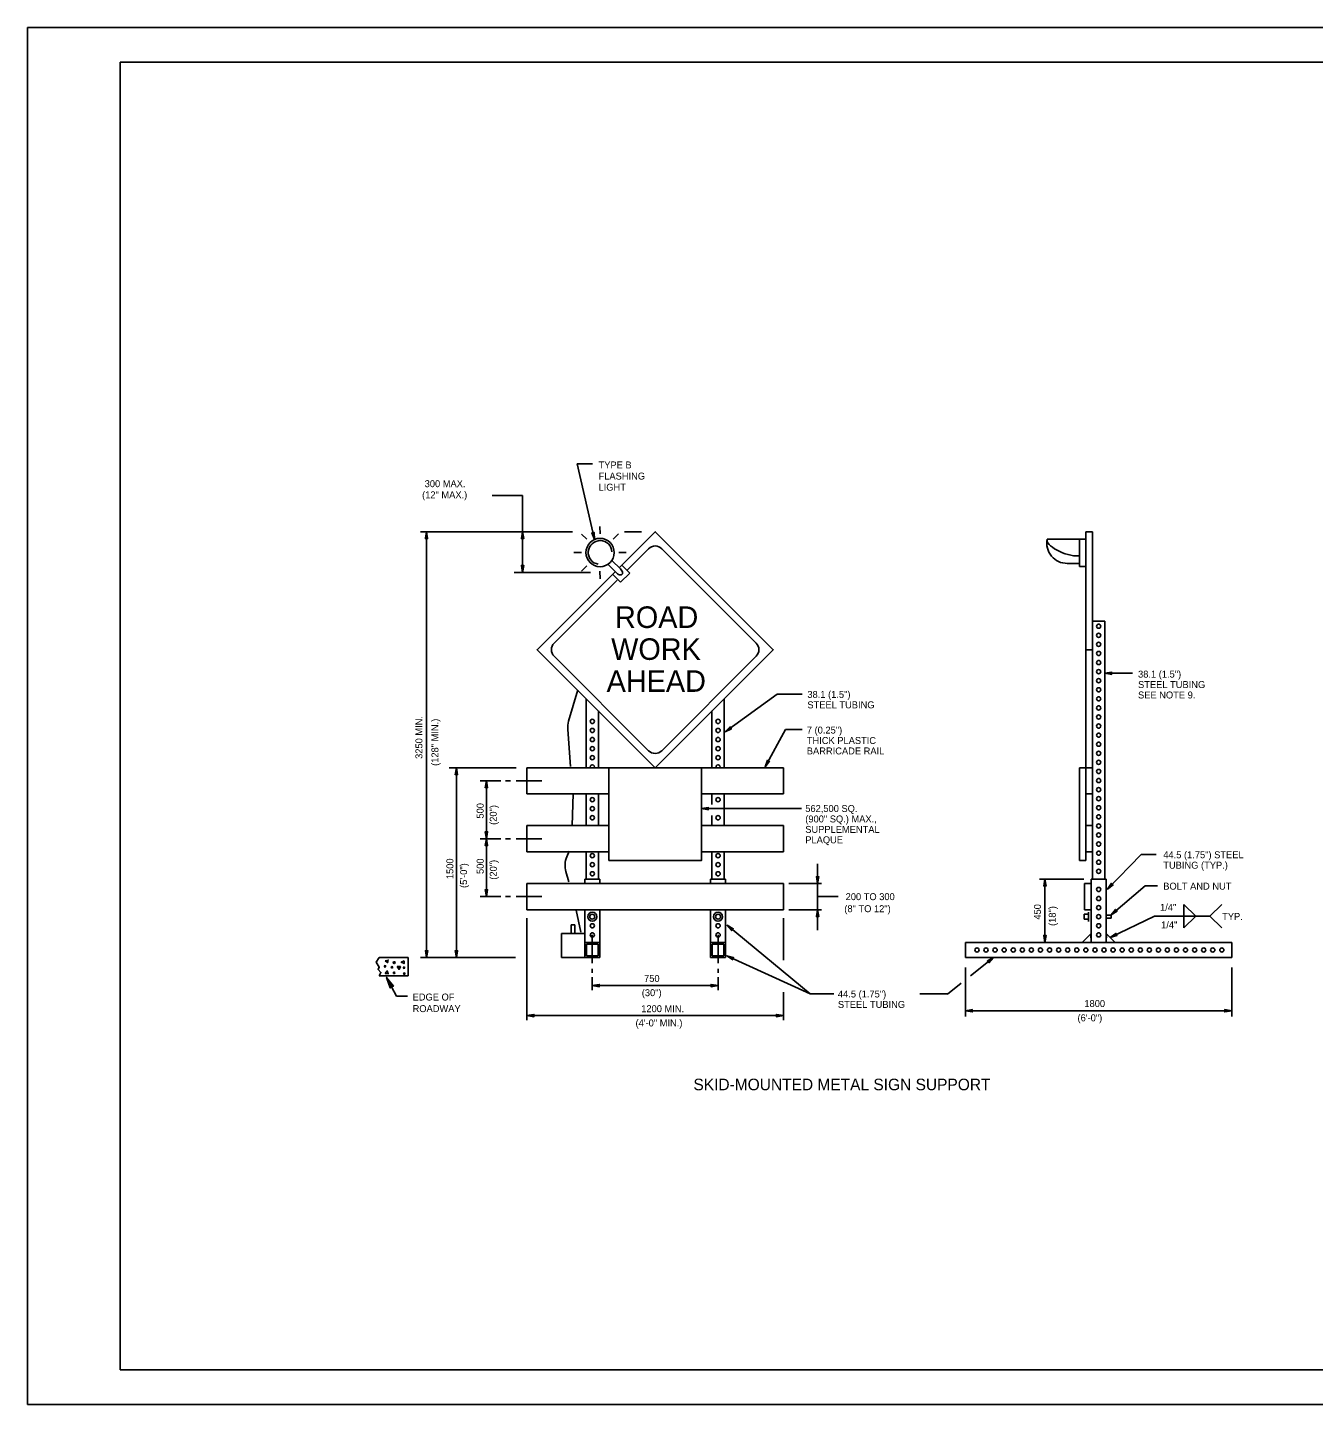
# Model space of a CAD drawing. Extents: x 641885 to 642995, y 293121 to 294294.
# Drawn here: x 641885 to 642440, y 293700 to 294294 of the extents above; entities that cross this region are included whole.
import ezdxf

# ---------------------------------------------------------------- set-up
doc = ezdxf.new("R2010")
doc.units = 0
for name, color, linetype in [('1', 7, 'Continuous'), ('Default', 7, 'Continuous'), ('Level 1', 7, 'Continuous'), ('Level 2', 7, 'Continuous'), ('Level 3', 7, 'Continuous'), ('PLT-BNDY', 7, 'Continuous')]:
    doc.layers.add(name, color=color, linetype=linetype)

# ---------------------------------------------------------------- blocks, each defined once
blk = doc.blocks.new('RARROW')
at = {"layer": 'Level 3'}
blk.add_lwpolyline([(-2.2695, 0.285), (-2.184875, 0.12075), (0, 0), (-2.2695, 0.285), (-2.38575, 0.384625), (0, 0), (-2.183125, -0.108), (-2.262875, -0.2705), (0, 0), (-2.38575, -0.379125), (-2.262875, -0.2705)], dxfattribs=at)

msp = doc.modelspace()

# ---------------------------------------------------------------- linework, layer by layer
at = {"layer": '1'}
for p, q in [((642384.2, 293910.28), (642384.2, 293915.37)), ((642389.3, 293910.28), (642384.2, 293915.37)), ((642395.44, 293910.28), (642400.54, 293915.37)), ((642371.58, 293910.28), (642395.44, 293910.28)), ((642384.2, 293910.28), (642384.2, 293905.18)), ((642389.3, 293910.28), (642384.2, 293905.18)), ((642395.44, 293910.28), (642400.54, 293905.18)), ((642040.24, 293883.86), (642044.56, 293875.8))]:
    msp.add_line(p, q, dxfattribs=at)
for points in [[(642037.06, 293892.46), (642035.66, 293890.45), (642037.02, 293888.25), (642036.56, 293887.27), (642037.78, 293885.98), (642037.06, 293884.47)], [(642041.88, 293879.59), (642042.09, 293879.89), (642040.24, 293883.86), (642041.88, 293879.59), (642041.81, 293879.29), (642040.24, 293883.86), (642042.49, 293880.11), (642042.85, 293880.13), (642040.24, 293883.86), (642043.16, 293880.01), (642042.85, 293880.13)]]:
    msp.add_lwpolyline(points, dxfattribs=at)
for points in [[(642039.67, 293890.98), (642040.96, 293891.36), (642040.65, 293890.22)], [(642044.74, 293888.56), (642046.18, 293888.56), (642045.58, 293887.27)], [(642047.77, 293891.06), (642047.77, 293889.84), (642046.56, 293890.37)], [(642039.59, 293885.6), (642040.96, 293885.45), (642040.5, 293886.66)]]:
    msp.add_lwpolyline(points, close=True, dxfattribs=at)
for centre, radius in [((642039.59, 293888.63), 0.321), ((642042.55, 293888.25), 0.321), ((642043.53, 293890.22), 0.408), ((642047.77, 293888.03), 0.321), ((642043.46, 293885.83), 0.321), ((642047.85, 293885.53), 0.321)]:
    msp.add_circle(centre, radius, dxfattribs=at)
at = {"layer": 'Default'}
for p, q in [((642049.48, 293892.46), (642037.06, 293892.46)), ((642049.48, 293892.46), (642049.48, 293884.47)), ((642049.48, 293884.47), (642037.06, 293884.47)), ((642044.56, 293875.8), (642049.17, 293875.8))]:
    msp.add_line(p, q, dxfattribs=at)
at = {"layer": 'Level 1'}
for p, q in [((641925.31, 294278.63), (642711.31, 294278.63)), ((641925.31, 294278.63), (641925.31, 293714.63)), ((642711.31, 293714.63), (641925.31, 293714.63)), ((641925.31, 293714.63), (642511.31, 293714.63))]:
    msp.add_line(p, q, dxfattribs=at)
at = {"layer": 'Level 2'}
for p, q in [((642122.46, 294105.39), (642129.1, 294105.39)), ((642122.46, 294105.39), (642129.94, 294072.78)), ((642085.79, 294091.69), (642098.9, 294091.69)), ((642098.9, 294091.69), (642098.9, 294058.57)), ((642132.3, 294075.22), (642132.28, 294078.43)), ((642054.87, 294076.13), (642120.37, 294076.13)), ((642057.44, 293892.46), (642057.44, 294076.13)), ((642126.6, 294072.84), (642124.32, 294075.09)), ((642138.01, 294072.88), (642140.27, 294075.15)), ((642142.84, 294076.13), (642150.19, 294076.13)), ((642325.24, 294072.95), (642341.94, 294072.95)), ((642339.12, 294072.95), (642339.12, 294061.13)), ((642341.94, 294076.13), (642341.94, 293974.31)), ((642341.94, 294076.13), (642344.76, 294076.13)), ((642344.76, 294076.13), (642344.76, 293974.31)), ((642124.25, 294067.12), (642121.05, 294067.11)), ((642140.4, 294067.18), (642143.6, 294067.19)), ((642153.27, 294068.8), (642144.17, 294059.69)), ((642199.67, 294028.05), (642158.92, 294068.8)), ((642126.56, 294061.44), (642124.31, 294059.17)), ((642139.37, 294058.38), (642135.7, 294062.06)), ((642141.1, 294060.1), (642137.42, 294063.78)), ((642145.17, 294058.29), (642141.71, 294061.75)), ((642333.91, 294062.46), (642339.12, 294062.46)), ((642339.12, 294061.13), (642341.94, 294061.13)), ((642095.3, 294058.57), (642128.15, 294058.57)), ((642139.64, 294055.17), (642112.52, 294028.05)), ((642132.29, 294059.04), (642132.3, 294055.84)), ((642141.18, 294054.31), (642137.73, 294057.77)), ((642141.18, 294054.31), (642145.17, 294058.29)), ((642344.76, 294037.6), (642350.06, 294037.6)), ((642350.06, 294037.6), (642350.06, 293926.28)), ((642341.94, 294025.22), (642344.76, 294025.22)), ((642112.52, 294022.39), (642153.27, 293981.65)), ((642158.92, 293981.65), (642199.67, 294022.39)), ((642350.06, 294015.06), (642362.08, 294015.06)), ((642122.69, 294007.93), (642118.76, 293994.37)), ((642126.31, 294004.1), (642126.31, 293974.31)), ((642185.88, 294004.1), (642185.88, 293974.31)), ((642208.67, 294005.98), (642186.27, 293989.8)), ((642208.67, 294005.98), (642219.48, 294005.98)), ((642131.61, 293998.79), (642131.61, 293974.31)), ((642180.58, 293998.79), (642180.58, 293974.31)), ((642118.39, 293990.87), (642119.53, 293974.79)), ((642212.27, 293990.85), (642203.55, 293974.67)), ((642212.27, 293990.85), (642219.44, 293990.85)), ((642067.19, 293974.31), (642096.15, 293974.31)), ((642070.37, 293892.46), (642070.37, 293974.31)), ((642100.79, 293974.31), (642136.1, 293974.31)), ((642100.79, 293974.31), (642100.79, 293963)), ((642211.4, 293974.31), (642176.1, 293974.31)), ((642211.4, 293974.31), (642211.4, 293963)), ((642339.12, 293974.31), (642344.76, 293974.31)), ((642339.12, 293974.31), (642339.12, 293934.31)), ((642341.94, 293974.31), (642341.94, 293934.31)), ((642344.76, 293974.31), (642344.76, 293926.28)), ((642089.48, 293968.66), (642080.61, 293968.66)), ((642083.3, 293943.69), (642083.3, 293968.66)), ((642093.67, 293968.66), (642091.45, 293968.66)), ((642107.21, 293968.66), (642096.13, 293968.66)), ((642100.79, 293963), (642136.1, 293963)), ((642120.7, 293963), (642120.25, 293949.34)), ((642126.31, 293963), (642126.31, 293949.34)), ((642131.61, 293963), (642131.61, 293949.34)), ((642211.4, 293963), (642176.1, 293963)), ((642180.58, 293963), (642180.58, 293958.46)), ((642185.88, 293963), (642185.88, 293949.34)), ((642341.94, 293963), (642344.76, 293963)), ((642176.1, 293956.68), (642219.2, 293956.68)), ((642180.58, 293953.71), (642180.58, 293949.34)), ((642100.79, 293949.34), (642136.1, 293949.34)), ((642100.79, 293949.34), (642100.79, 293938.03)), ((642211.4, 293949.34), (642176.1, 293949.34)), ((642211.4, 293949.34), (642211.4, 293938.03)), ((642341.94, 293949.34), (642344.76, 293949.34)), ((642089.48, 293943.69), (642080.61, 293943.69)), ((642083.3, 293918.71), (642083.3, 293943.69)), ((642093.67, 293943.69), (642091.45, 293943.69)), ((642107.21, 293943.69), (642096.13, 293943.69)), ((642100.79, 293938.03), (642136.1, 293938.03)), ((642118.95, 293938.35), (642117.95, 293935.92)), ((642126.31, 293938.03), (642126.31, 293926.28)), ((642131.61, 293938.03), (642131.61, 293926.28)), ((642211.4, 293938.03), (642176.1, 293938.03)), ((642180.58, 293938.03), (642180.58, 293926.28)), ((642185.88, 293938.03), (642185.88, 293926.28)), ((642341.94, 293938.03), (642344.76, 293938.03)), ((642351.23, 293921.97), (642365.7, 293936.86)), ((642365.7, 293936.86), (642372.29, 293936.86)), ((642117.56, 293929.5), (642118.78, 293925.03)), ((642226.18, 293924.37), (642226.18, 293932.79)), ((642339.12, 293934.31), (642341.94, 293934.31)), ((642100.79, 293924.37), (642211.4, 293924.37)), ((642100.79, 293924.37), (642100.79, 293913.06)), ((642132.21, 293926.28), (642125.71, 293926.28)), ((642125.71, 293924.37), (642125.71, 293926.28)), ((642132.21, 293924.37), (642132.21, 293926.28)), ((642186.48, 293926.28), (642179.98, 293926.28)), ((642179.98, 293924.37), (642179.98, 293926.28)), ((642186.48, 293924.37), (642186.48, 293926.28)), ((642211.4, 293924.37), (642211.4, 293913.06)), ((642213.69, 293924.37), (642227.87, 293924.37)), ((642226.18, 293913.06), (642226.18, 293924.37)), ((642321.91, 293926.28), (642341.05, 293926.28)), ((642324.23, 293898.96), (642324.23, 293926.28)), ((642344.16, 293924.37), (642341.34, 293924.37)), ((642341.34, 293924.37), (642341.34, 293913.06)), ((642344.16, 293926.28), (642344.16, 293898.96)), ((642344.16, 293926.28), (642350.66, 293926.28)), ((642350.66, 293926.28), (642350.66, 293898.96)), ((642352.77, 293910.89), (642367.46, 293923.42)), ((642367.46, 293923.42), (642372.86, 293923.42)), ((642089.48, 293918.71), (642080.61, 293918.71)), ((642093.67, 293918.71), (642091.45, 293918.71)), ((642107.21, 293918.71), (642096.13, 293918.71)), ((642226.18, 293918.71), (642235.1, 293918.71)), ((642100.79, 293913.06), (642211.4, 293913.06)), ((642122.07, 293912.89), (642124.01, 293903.39)), ((642125.71, 293892.46), (642125.71, 293913.06)), ((642132.21, 293892.46), (642132.21, 293913.06)), ((642179.98, 293892.46), (642179.98, 293913.06)), ((642186.48, 293892.46), (642186.48, 293913.06)), ((642213.69, 293913.06), (642227.87, 293913.06)), ((642226.18, 293904.26), (642226.18, 293913.06)), ((642344.16, 293913.06), (642341.34, 293913.06)), ((642343.07, 293912.02), (642343.07, 293907.92)), ((642100.79, 293865.41), (642100.79, 293909.38)), ((642119.86, 293902.8), (642119.86, 293906.5)), ((642119.86, 293906.5), (642121.46, 293906.5)), ((642121.46, 293902.8), (642121.46, 293906.5)), ((642223, 293876.74), (642187.13, 293906.38)), ((642211.4, 293891.25), (642211.4, 293909.38)), ((642343.07, 293911.11), (642341.23, 293911.11)), ((642341.23, 293911.11), (642341.23, 293908.97)), ((642343.07, 293908.97), (642341.23, 293908.97)), ((642352.82, 293910.66), (642350.66, 293910.66)), ((642352.82, 293909.42), (642350.66, 293909.42)), ((642352.41, 293901.05), (642371.58, 293910.28)), ((642352.82, 293910.66), (642352.82, 293909.42)), ((642115.61, 293902.8), (642125.71, 293902.8)), ((642115.61, 293902.8), (642115.61, 293892.46)), ((642125.71, 293902.8), (642125.71, 293892.46)), ((642128.96, 293890.04), (642128.96, 293902.21)), ((642183.23, 293890.04), (642183.23, 293902.21)), ((642132.21, 293898.96), (642125.71, 293898.96)), ((642126.46, 293893.21), (642126.46, 293898.21)), ((642131.46, 293898.21), (642126.46, 293898.21)), ((642131.46, 293893.21), (642131.46, 293898.21)), ((642186.48, 293898.96), (642179.98, 293898.96)), ((642180.73, 293893.21), (642180.73, 293898.21)), ((642185.73, 293898.21), (642180.73, 293898.21)), ((642185.73, 293893.21), (642185.73, 293898.21)), ((642289.96, 293898.96), (642404.86, 293898.96)), ((642289.96, 293898.96), (642289.96, 293892.46)), ((642404.86, 293898.96), (642404.86, 293892.46)), ((642054.87, 293892.46), (642095.88, 293892.46)), ((642115.61, 293892.46), (642125.71, 293892.46)), ((642132.21, 293892.46), (642125.71, 293892.46)), ((642131.46, 293893.21), (642126.46, 293893.21)), ((642128.96, 293885.8), (642128.96, 293887.52)), ((642186.48, 293892.46), (642179.98, 293892.46)), ((642185.73, 293893.21), (642180.73, 293893.21)), ((642183.23, 293885.8), (642183.23, 293887.52)), ((642223, 293876.74), (642187.02, 293893.19)), ((642289.96, 293892.46), (642404.86, 293892.46)), ((642289.96, 293867.01), (642289.96, 293888.2)), ((642292.13, 293884.57), (642302.1, 293892.46)), ((642404.86, 293867.01), (642404.86, 293888.2)), ((642128.96, 293878.34), (642128.96, 293883.89)), ((642183.23, 293878.34), (642183.23, 293883.89)), ((642128.96, 293880.31), (642183.23, 293880.31)), ((642211.4, 293865.41), (642211.4, 293877.44)), ((642223, 293876.74), (642233.15, 293876.74)), ((642270.25, 293876.74), (642282.25, 293876.74)), ((642282.18, 293876.69), (642288.11, 293881.38)), ((642100.79, 293867.38), (642211.4, 293867.38)), ((642289.96, 293869.48), (642404.86, 293869.48))]:
    msp.add_line(p, q, dxfattribs=at)
msp.add_lwpolyline([(642138.62, 294058.66), (642105.18, 294025.22), (642156.1, 293974.31), (642207.01, 294025.22), (642156.1, 294076.13), (642140.65, 294060.69)], dxfattribs=at)
for points in [[(642136.1, 293934.31), (642176.1, 293934.31), (642176.1, 293974.31), (642136.1, 293974.31)], [(642344.16, 293898.96), (642340.33, 293898.91), (642344.02, 293902.61)], [(642350.66, 293898.96), (642354.49, 293898.91), (642350.79, 293902.61)]]:
    msp.add_lwpolyline(points, close=True, dxfattribs=at)
for centre, radius in [((642132.33, 294067.15), 6.11), ((642347.41, 294035.36), 0.903), ((642347.41, 294031.44), 0.903), ((642347.41, 294027.52), 0.903), ((642347.41, 294023.61), 0.903), ((642347.41, 294019.69), 0.903), ((642347.41, 294015.77), 0.903), ((642347.41, 294011.86), 0.903), ((642347.41, 294007.94), 0.903), ((642347.41, 294004.03), 0.903), ((642347.41, 294000.11), 0.903), ((642128.96, 293994.29), 0.903), ((642183.23, 293994.29), 0.903), ((642347.41, 293996.19), 0.903), ((642128.96, 293990.38), 0.903), ((642183.23, 293990.38), 0.903), ((642347.41, 293992.28), 0.903), ((642347.41, 293988.36), 0.903), ((642128.96, 293986.46), 0.903), ((642128.96, 293982.54), 0.903), ((642183.23, 293986.46), 0.903), ((642183.23, 293982.54), 0.903), ((642347.41, 293984.45), 0.903), ((642128.96, 293978.63), 0.903), ((642183.23, 293978.63), 0.903), ((642347.41, 293980.53), 0.903), ((642347.41, 293976.61), 0.903), ((642347.41, 293972.7), 0.903), ((642347.41, 293968.78), 0.903), ((642347.41, 293964.87), 0.903), ((642128.96, 293960.56), 0.903), ((642183.23, 293960.56), 0.903), ((642347.41, 293960.95), 0.903), ((642128.96, 293956.65), 0.903), ((642128.96, 293952.73), 0.903), ((642183.23, 293952.73), 0.903), ((642347.41, 293957.03), 0.903), ((642347.41, 293953.12), 0.903), ((642347.41, 293949.2), 0.903), ((642347.41, 293945.28), 0.903), ((642347.41, 293941.37), 0.903), ((642128.96, 293936.39), 0.903), ((642183.23, 293936.39), 0.903), ((642347.41, 293937.45), 0.903), ((642128.96, 293932.47), 0.903), ((642128.96, 293928.56), 0.903), ((642183.23, 293932.47), 0.903), ((642183.23, 293928.56), 0.903), ((642347.41, 293933.54), 0.903), ((642347.41, 293929.62), 0.903), ((642347.41, 293921.79), 0.903), ((642347.41, 293917.87), 0.903), ((642128.96, 293910.04), 1.93), ((642183.23, 293910.04), 1.93), ((642347.41, 293913.96), 0.903), ((642128.96, 293910.04), 1.07), ((642128.96, 293906.12), 0.903), ((642183.23, 293910.04), 1.07), ((642183.23, 293906.12), 0.903), ((642347.41, 293910.04), 0.903), ((642347.41, 293906.12), 0.903), ((642128.96, 293902.21), 0.903), ((642183.23, 293902.21), 0.903), ((642347.41, 293902.21), 0.903), ((642294.91, 293895.71), 0.903), ((642298.83, 293895.71), 0.903), ((642302.74, 293895.71), 0.903), ((642306.66, 293895.71), 0.903), ((642310.58, 293895.71), 0.903), ((642314.49, 293895.71), 0.903), ((642318.41, 293895.71), 0.903), ((642322.32, 293895.71), 0.903), ((642326.24, 293895.71), 0.903), ((642330.16, 293895.71), 0.903), ((642334.07, 293895.71), 0.903), ((642337.99, 293895.71), 0.903), ((642341.9, 293895.71), 0.903), ((642345.82, 293895.71), 0.903), ((642349.74, 293895.71), 0.903), ((642353.65, 293895.71), 0.903), ((642357.57, 293895.71), 0.903), ((642361.49, 293895.71), 0.903), ((642365.4, 293895.71), 0.903), ((642369.32, 293895.71), 0.903), ((642373.23, 293895.71), 0.903), ((642377.07, 293895.71), 0.903), ((642380.99, 293895.71), 0.903), ((642384.9, 293895.71), 0.903), ((642388.82, 293895.71), 0.903), ((642392.74, 293895.71), 0.903), ((642396.65, 293895.71), 0.903), ((642400.57, 293895.71), 0.903)]:
    msp.add_circle(centre, radius, dxfattribs=at)
for centre, radius, start, end in [((642132.33, 294067.15), 5.12, 2.99859, 260.92051), ((642333.79, 294071.19), 8.73, 168.39588, 270.8338), ((642156.1, 294065.97), 4, 44.99999, 135), ((642115.35, 294025.22), 4, 135, 225), ((642196.84, 294025.22), 4, 314.99967, 44.99998), ((642128.36, 293991.58), 10, 163.81078, 184.07684), ((642156.1, 293984.48), 4, 224.99984, 315.0003), ((642128.96, 293974.71), 0.903, 350.18245, 189.46844), ((642183.23, 293974.71), 0.903, 350.53156, 189.81755), ((642127.21, 293932.13), 10, 157.72787, 195.25958)]:
    msp.add_arc(centre, radius, start, end, dxfattribs=at)
for centre, major_axis, ratio, start_param, end_param in [((642333.25, 294069.93), (8.01, -3.02), 0.375725, 3.141593, 5.588182), ((642140.23, 294059.24), (1.54, -1.54), 0.560008, 4.712389, 7.853982)]:
    msp.add_ellipse(centre, major_axis=major_axis, ratio=ratio, start_param=start_param, end_param=end_param, dxfattribs=at)
at = {"layer": 'PLT-BNDY'}
msp.add_lwpolyline([(641885.31, 294293.63), (642726.31, 294293.63), (642726.31, 293699.63), (641885.31, 293699.63)], close=True, dxfattribs=at)

# ---------------------------------------------------------------- block references
at = {"layer": 'Level 2'}
for p, xscale, yscale, rotation in [((642057.44, 294076.13), 1.2574347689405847, 1.3092961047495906, 89.99999999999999), ((642098.9, 294076.13), 1.2574347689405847, 1.3092961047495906, 89.99999999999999), ((642129.94, 294072.78), 1.257434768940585, 1.3092961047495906, -76.65647202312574), ((642098.9, 294058.57), 1.2574347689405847, 1.3092961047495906, -90.00000000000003), ((642350.06, 294015.06), 1.2574347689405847, 1.3092961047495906, 180), ((642186.26, 293989.8), 1.257434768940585, 1.3092961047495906, -143.95284350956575), ((642203.55, 293974.67), 1.2574347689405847, 1.3092961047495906, -118.29722389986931), ((642070.37, 293974.31), 1.2574347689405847, 1.3092961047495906, 89.99999999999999), ((642083.3, 293968.66), 1.2574347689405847, 1.3092961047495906, 89.99999999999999), ((642176.1, 293956.68), 1.2574347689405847, 1.3092961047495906, 180), ((642083.3, 293943.69), 1.2574347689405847, 1.3092961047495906, -90.00000000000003), ((642083.3, 293943.69), 1.2574347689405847, 1.3092961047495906, 89.99999999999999), ((642226.18, 293924.37), 1.2574347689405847, 1.3092961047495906, -90.00000000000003), ((642324.22, 293926.28), 1.2574347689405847, 1.3092961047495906, 89.99999999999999), ((642351.23, 293921.97), 1.2574347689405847, 1.3092961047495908, -134.20874209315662), ((642083.3, 293918.72), 1.2574347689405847, 1.3092961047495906, -90.00000000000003), ((642226.18, 293913.06), 1.2574347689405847, 1.3092961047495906, 89.99999999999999), ((642352.77, 293910.89), 1.2574347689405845, 1.3092961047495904, -139.54557767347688), ((642187.13, 293906.38), 1.2574347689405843, 1.3092961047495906, 140.2360200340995), ((642324.22, 293898.96), 1.2574347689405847, 1.3092961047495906, -90.00000000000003), ((642352.41, 293901.05), 1.2574347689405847, 1.3092961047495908, -154.2997184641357), ((642057.44, 293892.46), 1.2574347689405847, 1.3092961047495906, -90.00000000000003), ((642070.37, 293892.46), 1.2574347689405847, 1.3092961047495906, -90.00000000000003), ((642187.02, 293893.19), 1.2574347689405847, 1.3092961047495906, 155.22886209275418), ((642302.1, 293892.46), 1.257434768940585, 1.3092961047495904, 38.5772109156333), ((642128.96, 293880.31), 1.2574347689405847, 1.3092961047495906, 180), ((642289.96, 293869.48), 1.2574347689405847, 1.3092961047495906, 180), ((642100.79, 293867.38), 1.2574347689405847, 1.3092961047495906, 180)]:
    msp.add_blockref('RARROW', p, dxfattribs=dict(at, xscale=xscale, yscale=yscale, rotation=rotation))
at = {"layer": 'Level 2', "xscale": 1.2574347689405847, "yscale": 1.3092961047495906}
for p in [(642183.23, 293880.31), (642404.86, 293869.48), (642211.4, 293867.38)]:
    msp.add_blockref('RARROW', p, dxfattribs=at)

# ---------------------------------------------------------------- texts
at = {"layer": '1'}
for s, p in [('1/4"', (642373.92, 293912.59)), ('TYP.', (642400.72, 293908.65)), ('1/4"', (642374.37, 293905.02)), ('EDGE OF ', (642051.44, 293873.89)), ('ROADWAY', (642051.44, 293868.89))]:
    msp.add_text(s, height=3, dxfattribs=at).set_placement(p)
at = {"layer": 'Level 2'}
for s, height, p in [('TYPE B', 3, (642131.66, 294103.43)), ('FLASHING', 3, (642131.66, 294098.63)), (' 300 MAX.', 3, (642055.53, 294095.34)), ('LIGHT', 3, (642131.66, 294093.83)), ('(12" MAX.)', 3, (642055.53, 294090.54)), ('ROAD', 9.301, (642138.76, 294034.61)), ('WORK', 9.301, (642137.1, 294020.83)), ('AHEAD', 9.301, (642135.15, 294007.05)), ('38.1 (1.5")', 3, (642364.42, 294013.19)), ('38.1 (1.5")', 3, (642221.76, 294004.44)), ('STEEL TUBING', 3, (642364.42, 294008.69)), ('SEE NOTE 9.', 3, (642364.42, 294004.19)), ('STEEL TUBING', 3, (642221.76, 293999.94)), ('7 (0.25")', 3, (642221.52, 293989.05)), ('THICK PLASTIC', 3, (642221.52, 293984.55)), ('BARRICADE RAIL', 3, (642221.52, 293980.05)), ('562,500 SQ.', 3, (642220.85, 293955.21)), ('(900" SQ.) MAX.,', 3, (642220.85, 293950.71)), ('SUPPLEMENTAL', 3, (642220.85, 293946.21)), ('PLAQUE', 3, (642220.85, 293941.71)), ('44.5 (1.75") STEEL', 3, (642375.31, 293935.26)), ('TUBING (TYP.)', 3, (642375.31, 293930.76)), ('BOLT AND NUT', 3, (642375.29, 293921.72)), ('750', 3, (642151.31, 293881.92)), ('(30")', 3, (642150.32, 293875.76)), ('44.5 (1.75")', 3, (642234.93, 293875.2)), ('1200 MIN.', 3, (642150.08, 293868.86)), ('STEEL TUBING', 3, (642234.93, 293870.7)), ('1800', 3, (642341.27, 293871.08)), ('(4\'-0" MIN.)', 3, (642147.61, 293862.7)), ('(6\'-0")', 3, (642338.31, 293864.92)), ('SKID-MOUNTED METAL SIGN SUPPORT', 5, (642172.6, 293835.17))]:
    msp.add_text(s, height=height, dxfattribs=at).set_placement(p)
for s, rotation, p in [('3250 MIN.', 90, (642055.67, 293978.12)), ('(128" MIN.)', 90, (642062.59, 293975.1)), ('500', 90, (642082.09, 293952.37)), ('(20")', 90, (642087.75, 293949.66)), ('1500', 90, (642069.03, 293926.26)), ('500', 90, (642082.09, 293928.47)), ('(5\'-0")', 90, (642074.94, 293922.45)), ('(20")', 90, (642087.75, 293926.01)), ('200 TO 300', 360, (642238.26, 293917.19)), ('(8" TO 12")', 360, (642237.7, 293912)), ('450', 90, (642322.52, 293908.77)), ('(18")', 90, (642328.92, 293906.06))]:
    msp.add_text(s, height=3, rotation=rotation, dxfattribs=at).set_placement(p)

doc.saveas('drawing.dxf')
